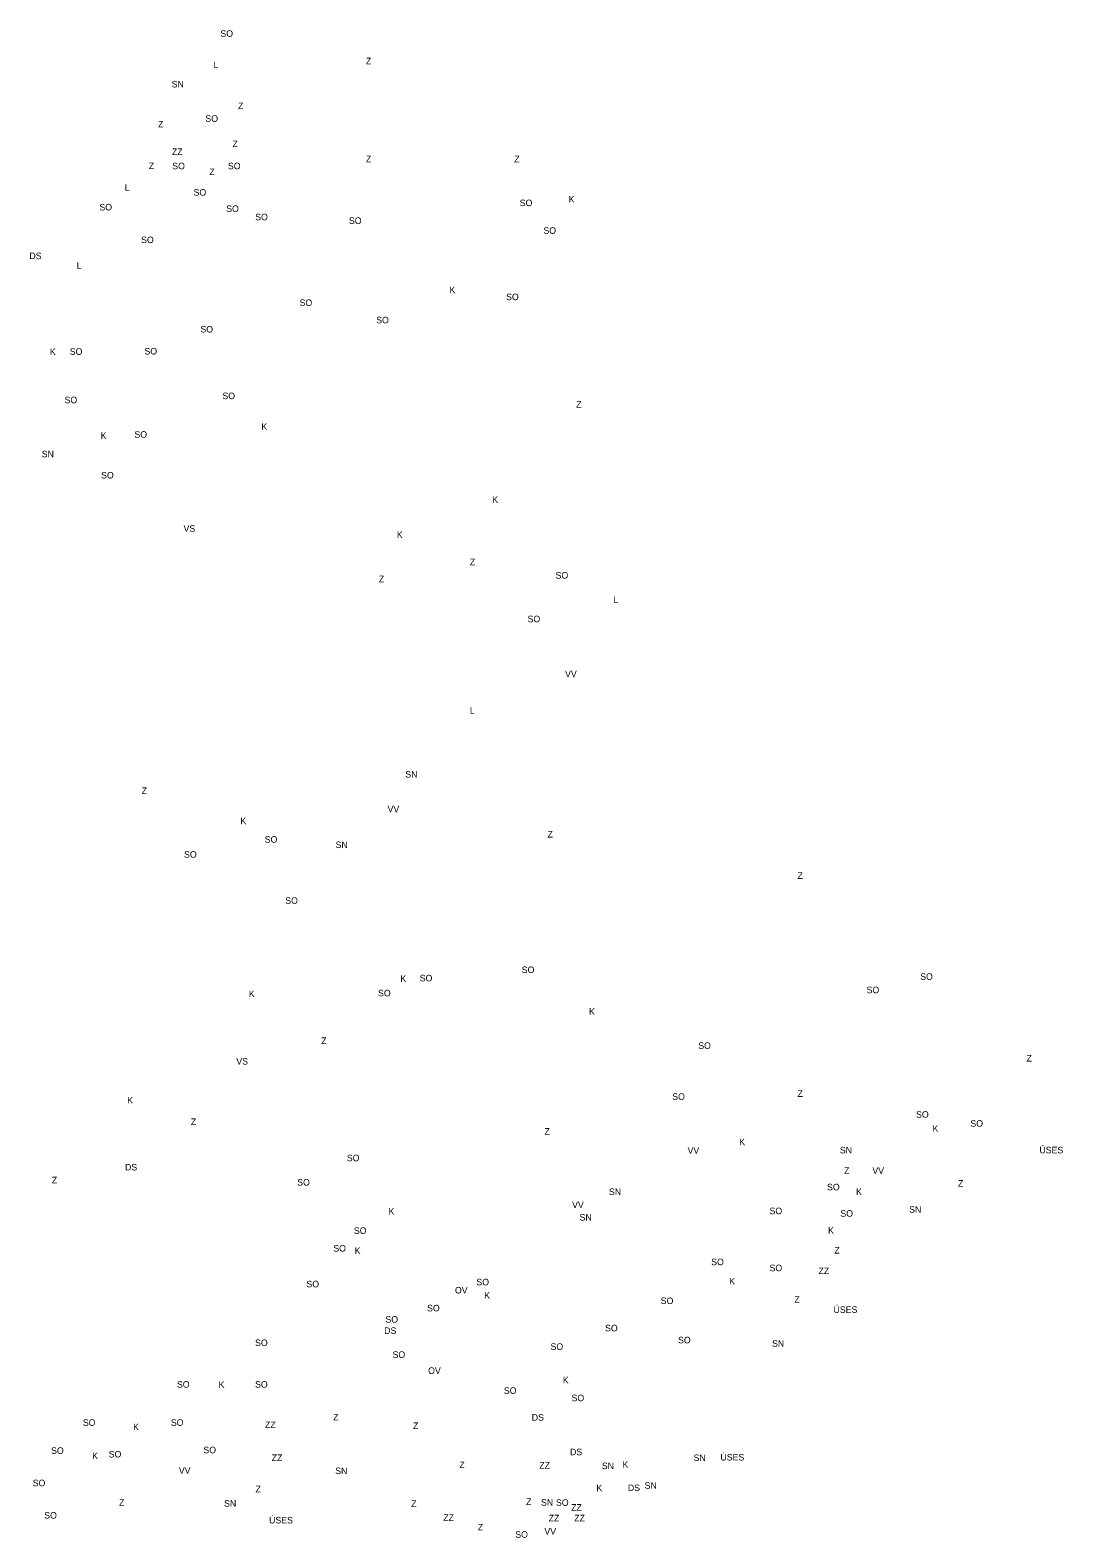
# Model space of a CAD drawing. Extents: x -445021 to -431236, y -1134464 to -1129615.
# Drawn here: x -442128 to -440551, y -1132144 to -1129841 of the extents above; entities that cross this region are included whole.
import ezdxf

# ---------------------------------------------------------------- set-up
doc = ezdxf.new("R2010")
doc.units = 0
doc.layers.add('Vrstva 4', color=7, linetype='Continuous')

msp = doc.modelspace()

# ---------------------------------------------------------------- texts
at = {"layer": 'Vrstva 4'}
for s, p in [('SO', (-441837.9, -1129850.8)), ('L', (-441848.5, -1129898.6)), ('Z', (-441615.6, -1129892.8)), ('SN', (-441912.3, -1129928.1)), ('Z', (-441810.9, -1129961.2)), ('Z', (-441933.1, -1129989.2)), ('SO', (-441860.8, -1129980.6)), ('ZZ', (-441911.9, -1130031.3)), ('Z', (-441819.5, -1130019.3)), ('Z', (-441947.3, -1130052.9)), ('SO', (-441911.4, -1130053.1)), ('Z', (-441854.7, -1130062)), ('SO', (-441826.4, -1130053.1)), ('Z', (-441615.6, -1130042.4)), ('Z', (-441389.1, -1130042.4)), ('L', (-441984, -1130086)), ('SO', (-441878.9, -1130093.4)), ('SO', (-441380.7, -1130109.4)), ('K', (-441305.9, -1130103.8)), ('SO', (-442022.7, -1130116)), ('SO', (-441829, -1130118.3)), ('SO', (-441784.7, -1130131)), ('SO', (-441641.6, -1130136.6)), ('SO', (-441344.5, -1130151.7)), ('SO', (-441959, -1130165.9)), ('DS', (-442129.6, -1130190.4)), ('L', (-442057.3, -1130205.1)), ('K', (-441488, -1130242.4)), ('SO', (-441716.9, -1130261.9)), ('SO', (-441401.5, -1130253)), ('SO', (-441599.9, -1130288.4)), ('SO', (-441868.4, -1130302.4)), ('K', (-442098.3, -1130336.8)), ('SO', (-442068, -1130336.5)), ('SO', (-441953.9, -1130336)), ('SO', (-441834.8, -1130404.2)), ('SO', (-442075.9, -1130410.5)), ('Z', (-441294.4, -1130417.1)), ('K', (-441775.3, -1130451.1)), ('K', (-442020.7, -1130465.1)), ('SO', (-441969.2, -1130463.2)), ('SN', (-442110.8, -1130493.1)), ('SO', (-442020.1, -1130525.4)), ('K', (-441422.6, -1130562.7)), ('VS', (-441894.2, -1130606.9)), ('K', (-441568.4, -1130616.3)), ('Z', (-441456.9, -1130658)), ('Z', (-441595.8, -1130683.9)), ('SO', (-441325.9, -1130678.3)), ('L', (-441237.4, -1130715.5)), ('SO', (-441368.7, -1130745)), ('VV', (-441311.4, -1130829)), ('L', (-441456.9, -1130884.5)), ('SN', (-441555.4, -1130982.3)), ('Z', (-441958.1, -1131007.4)), ('K', (-441807.3, -1131053.5)), ('VV', (-441582.5, -1131035.4)), ('Z', (-441338.2, -1131073.9)), ('SO', (-441770.2, -1131081.8)), ('SN', (-441662, -1131090)), ('SO', (-441893.4, -1131104.7)), ('Z', (-440956.4, -1131137)), ('SO', (-441738.8, -1131175.2)), ('SO', (-441377.6, -1131280.9)), ('K', (-441563, -1131294.4)), ('SO', (-441533.4, -1131293.6)), ('SO', (-440769, -1131291.3)), ('K', (-441794.4, -1131317.6)), ('SO', (-441597.1, -1131316.5)), ('SO', (-440850.9, -1131311.7)), ('K', (-441274.7, -1131344.5)), ('Z', (-441683.9, -1131389.3)), ('SO', (-441108, -1131396.7)), ('VS', (-441813.6, -1131420.7)), ('Z', (-440606.6, -1131416)), ('K', (-441980.1, -1131480.1)), ('SO', (-441147.7, -1131474.6)), ('Z', (-440956.4, -1131470)), ('Z', (-441883, -1131513)), ('SO', (-440775.3, -1131501.9)), ('SO', (-440692.3, -1131515.6)), ('Z', (-441342.8, -1131527.8)), ('K', (-440750.1, -1131523.4)), ('VV', (-441124.3, -1131556.9)), ('K', (-441045.4, -1131543.8)), ('SN', (-440891.7, -1131556.4)), ('ÚSES', (-440586.9, -1131556.3)), ('DS', (-441983.6, -1131582.4)), ('SO', (-441644.7, -1131568.3)), ('Z', (-442095.3, -1131602.1)), ('SO', (-441720.5, -1131605.5)), ('Z', (-440885.1, -1131587.4)), ('VV', (-440842, -1131587.7)), ('Z', (-440711.2, -1131607.2)), ('SN', (-441244.4, -1131619.9)), ('SO', (-440911.3, -1131612.8)), ('K', (-440866.9, -1131619.9)), ('K', (-441581.1, -1131649.8)), ('VV', (-441300.7, -1131639.9)), ('SO', (-440999.1, -1131649.2)), ('SO', (-440890.9, -1131653.1)), ('SN', (-440785.8, -1131647)), ('SN', (-441289.3, -1131659)), ('SO', (-441634, -1131679.3)), ('K', (-440909.7, -1131678.9)), ('SO', (-441665.5, -1131706.3)), ('K', (-441632.8, -1131709.9)), ('Z', (-440900.1, -1131709.3)), ('SO', (-441088.2, -1131727.1)), ('SO', (-440999.1, -1131736.3)), ('ZZ', (-440924.4, -1131740.8)), ('SO', (-441706.5, -1131761)), ('SO', (-441446.9, -1131757.9)), ('K', (-441060.6, -1131756.6)), ('OV', (-441479.6, -1131770.3)), ('K', (-441434.8, -1131778.2)), ('SO', (-441165.3, -1131786.5)), ('Z', (-440961.2, -1131784.6)), ('SO', (-441585.8, -1131815)), ('SO', (-441522.2, -1131797.7)), ('ÚSES', (-440901.4, -1131800)), ('DS', (-441587.7, -1131832.1)), ('SO', (-441250.3, -1131828.2)), ('SO', (-441784.9, -1131850.6)), ('SO', (-441333.6, -1131856.5)), ('SO', (-441138.8, -1131846.5)), ('SN', (-440995.3, -1131851.7)), ('SO', (-441574.9, -1131868.7)), ('OV', (-441520.6, -1131893.2)), ('SO', (-441904.3, -1131914.2)), ('K', (-441840.6, -1131914.6)), ('SO', (-441784.9, -1131914.2)), ('SO', (-441404.9, -1131923.7)), ('K', (-441314.9, -1131907.5)), ('SO', (-441301.5, -1131934.9)), ('SO', (-442047.9, -1131972.5)), ('SO', (-441913.5, -1131972.5)), ('ZZ', (-441769.8, -1131975.9)), ('Z', (-441665.6, -1131964.2)), ('DS', (-441362.3, -1131964.6)), ('K', (-441971.2, -1131979.1)), ('Z', (-441543.7, -1131977.4)), ('SO', (-442096.5, -1132015.3)), ('SO', (-442008.5, -1132020.8)), ('SO', (-441863.9, -1132014.4)), ('DS', (-441303.9, -1132017.4)), ('K', (-442033.8, -1132023.4)), ('ZZ', (-441759.5, -1132026.2)), ('Z', (-441472.9, -1132037.1)), ('ZZ', (-441350.8, -1132037.9)), ('SN', (-441255.3, -1132038.6)), ('K', (-441223.7, -1132036.5)), ('SN', (-441115.2, -1132026.3)), ('ÚSES', (-441074.1, -1132025.4)), ('SO', (-442124.6, -1132064.8)), ('VV', (-441901.4, -1132045.7)), ('SN', (-441662.5, -1132046.2)), ('Z', (-441784.2, -1132074)), ('K', (-441263.5, -1132072.5)), ('DS', (-441215.5, -1132072.2)), ('SN', (-441189.9, -1132068.7)), ('SO', (-442107, -1132114.2)), ('Z', (-441992.7, -1132094.6)), ('SN', (-441832.3, -1132096)), ('Z', (-441546.5, -1132096.4)), ('Z', (-441371, -1132093.3)), ('SN', (-441348.2, -1132094.5)), ('SO', (-441325.3, -1132094.7)), ('ZZ', (-441302.1, -1132102.1)), ('ÚSES', (-441763.5, -1132121.6)), ('ZZ', (-441497.5, -1132117.7)), ('Z', (-441444.8, -1132132.3)), ('ZZ', (-441336.4, -1132118.4)), ('ZZ', (-441297.4, -1132118.4)), ('SO', (-441387.5, -1132143.5)), ('VV', (-441343, -1132138.7))]:
    msp.add_text(s, height=10, dxfattribs=at).set_placement(p)

doc.saveas('drawing.dxf')
